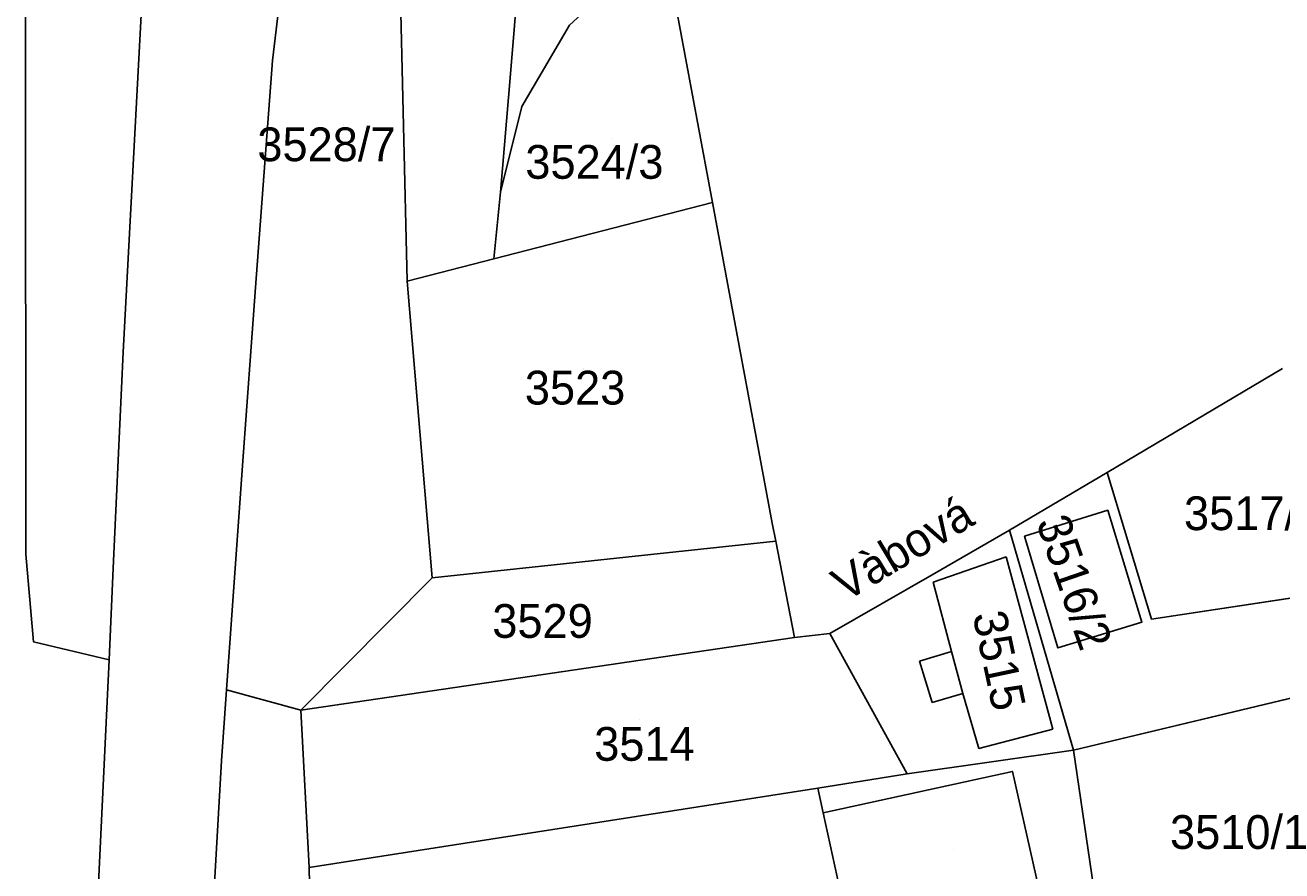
# Model space of a CAD drawing. Extents: x -262657 to -261595, y -1238015 to -1237156.
# Drawn here: x -262343.6 to -262269.2, y -1237443.2 to -1237393.1 of the extents above; entities that cross this region are included whole.
import ezdxf

# ---------------------------------------------------------------- set-up
doc = ezdxf.new("R2010")
doc.units = 0
for name, color, linetype in [('body_kn', 7, 'Continuous'), ('kladpar_druhypozemkov', 7, 'Continuous'), ('kladpar_hranice', 7, 'Continuous'), ('kladpar_parcelnecisla', 7, 'Continuous'), ('kladpar_plochy', 7, 'Continuous'), ('popisy', 7, 'Continuous'), ('zappar_hrandruhpozemk', 7, 'Continuous')]:
    doc.layers.add(name, color=color, linetype=linetype)

msp = doc.modelspace()

# ---------------------------------------------------------------- linework, layer by layer
at = {"layer": 'body_kn'}
for p, q in [((-262311.42, -1237393.12), (-262311.42, -1237393.12)), ((-262329, -1237395.2), (-262329, -1237395.2)), ((-262314.91, -1237395.99), (-262314.91, -1237395.99)), ((-262314.24, -1237397.93), (-262314.24, -1237397.93)), ((-262315.49, -1237403.01), (-262315.49, -1237403.01)), ((-262302.95, -1237403.62), (-262302.95, -1237403.62)), ((-262315.9, -1237406.95), (-262315.9, -1237406.95)), ((-262330, -1237408.65), (-262330, -1237408.65)), ((-262321.02, -1237408.27), (-262321.02, -1237408.27)), ((-262337.84, -1237412.47), (-262337.84, -1237412.47)), ((-262330.77, -1237419.19), (-262330.77, -1237419.19)), ((-262279.58, -1237419.6), (-262279.58, -1237419.6)), ((-262279.54, -1237421.84), (-262279.54, -1237421.84)), ((-262299.41, -1237422.61), (-262299.41, -1237422.61)), ((-262285.36, -1237423.02), (-262285.36, -1237423.02)), ((-262284.46, -1237423.38), (-262284.46, -1237423.38)), ((-262284.46, -1237423.38), (-262284.46, -1237423.38)), ((-262299.2, -1237423.67), (-262299.2, -1237423.67)), ((-262343.6, -1237424.44), (-262343.6, -1237424.44)), ((-262285.55, -1237424.61), (-262285.55, -1237424.61)), ((-262285.55, -1237424.61), (-262285.55, -1237424.61)), ((-262338.44, -1237425.28), (-262338.44, -1237425.28)), ((-262289.93, -1237425.67), (-262289.93, -1237425.67)), ((-262319.55, -1237425.85), (-262319.55, -1237425.85)), ((-262319.55, -1237425.85), (-262319.55, -1237425.85)), ((-262289.87, -1237426.11), (-262289.87, -1237426.11)), ((-262277.51, -1237428.47), (-262277.51, -1237428.47)), ((-262276.94, -1237428.3), (-262276.94, -1237428.3)), ((-262298.09, -1237429.37), (-262298.09, -1237429.37)), ((-262295.99, -1237429.15), (-262295.99, -1237429.15)), ((-262343.15, -1237429.64), (-262343.15, -1237429.64)), ((-262288.79, -1237430.21), (-262288.79, -1237430.21)), ((-262288.79, -1237430.21), (-262288.79, -1237430.21)), ((-262282.5, -1237430), (-262282.5, -1237430)), ((-262338.68, -1237430.7), (-262338.68, -1237430.7)), ((-262290.68, -1237430.78), (-262290.68, -1237430.78)), ((-262331.73, -1237432.47), (-262331.73, -1237432.47)), ((-262331.73, -1237432.47), (-262331.73, -1237432.47)), ((-262338.79, -1237433.17), (-262338.79, -1237433.17)), ((-262288.11, -1237432.69), (-262288.11, -1237432.69)), ((-262327.33, -1237433.68), (-262327.33, -1237433.68)), ((-262327.33, -1237433.68), (-262327.33, -1237433.68)), ((-262289.93, -1237433.23), (-262289.93, -1237433.23)), ((-262282.78, -1237434.8), (-262282.78, -1237434.8)), ((-262287.17, -1237435.95), (-262287.17, -1237435.95)), ((-262281.57, -1237436.05), (-262281.57, -1237436.05)), ((-262281.57, -1237436.05), (-262281.57, -1237436.05)), ((-262332.03, -1237436.68), (-262332.03, -1237436.68)), ((-262291.42, -1237437.45), (-262291.42, -1237437.45)), ((-262291.42, -1237437.45), (-262291.42, -1237437.45)), ((-262285.18, -1237437.31), (-262285.18, -1237437.31)), ((-262296.71, -1237438.31), (-262296.71, -1237438.31)), ((-262296.39, -1237439.77), (-262296.39, -1237439.77)), ((-262326.82, -1237443.01), (-262326.82, -1237443.01)), ((-262326.82, -1237443.01), (-262326.82, -1237443.01))]:
    msp.add_line(p, q, dxfattribs=at)
at = {"layer": 'kladpar_druhypozemkov'}
for p, q in [((-262324.82, -1237398.99), (-262324.82, -1237398.99)), ((-262308.92, -1237399.81), (-262308.92, -1237399.81)), ((-262310.6, -1237413.45), (-262310.6, -1237413.45)), ((-262271.41, -1237420.77), (-262271.41, -1237420.77)), ((-262280.17, -1237425.44), (-262280.17, -1237425.44)), ((-262312.44, -1237427.3), (-262312.44, -1237427.3)), ((-262285.33, -1237430.67), (-262285.33, -1237430.67)), ((-262307.25, -1237434.21), (-262307.25, -1237434.21)), ((-262271.75, -1237439.82), (-262271.75, -1237439.82)), ((-262288.7, -1237441.95), (-262288.7, -1237441.95))]:
    msp.add_line(p, q, dxfattribs=at)
at = {"layer": 'kladpar_hranice'}
for points in [[(-262343.34, -1237325.34), (-262331.8, -1237325.22), (-262331.36, -1237325.22), (-262332.05, -1237331.96), (-262333.22, -1237346.71), (-262335.95, -1237382.2), (-262336.73, -1237391.76), (-262337.84, -1237412.47), (-262338.44, -1237425.28), (-262338.68, -1237430.7), (-262343.15, -1237429.64), (-262343.6, -1237424.44), (-262343.65, -1237365.15), (-262343.34, -1237325.34)], [(-262331.73, -1237432.47), (-262330.77, -1237419.19), (-262330, -1237408.65), (-262329, -1237395.2), (-262326.86, -1237377.31), (-262323.22, -1237345.32), (-262321.9, -1237333.72), (-262320.95, -1237325.18), (-262318.82, -1237325.43), (-262321.14, -1237350.11), (-262321.67, -1237380.66), (-262321.02, -1237408.27), (-262319.55, -1237425.85), (-262327.33, -1237433.68), (-262331.73, -1237432.47)], [(-262321.14, -1237350.11), (-262318.82, -1237325.43), (-262312.37, -1237325.84), (-262308.92, -1237326.35), (-262309.26, -1237330), (-262311.14, -1237350.45), (-262311.85, -1237358.99), (-262314.91, -1237395.99), (-262315.49, -1237403.01), (-262315.9, -1237406.95), (-262321.02, -1237408.27), (-262321.67, -1237380.66), (-262321.14, -1237350.11)], [(-262343.65, -1237365.15), (-262343.6, -1237424.44), (-262343.15, -1237429.64), (-262338.68, -1237430.7), (-262338.79, -1237433.17), (-262339.94, -1237457.24), (-262341.34, -1237486.23), (-262339.66, -1237536.38)], [(-262326.86, -1237377.31), (-262329, -1237395.2), (-262330, -1237408.65), (-262330.77, -1237419.19), (-262331.73, -1237432.47), (-262332.03, -1237436.68), (-262333.57, -1237463.66), (-262334.8, -1237485.25), (-262334.58, -1237488.96), (-262332.58, -1237535.43), (-262332.11, -1237546.54), (-262332.06, -1237547.64), (-262339.28, -1237547.74), (-262339.33, -1237546.39), (-262339.66, -1237536.38), (-262341.34, -1237486.23), (-262339.94, -1237457.24), (-262338.79, -1237433.17), (-262338.68, -1237430.7), (-262338.44, -1237425.28), (-262337.84, -1237412.47), (-262336.73, -1237391.76)], [(-262305.73, -1237388.67), (-262302.95, -1237403.62), (-262315.9, -1237406.95), (-262315.49, -1237403.01), (-262314.24, -1237397.93), (-262311.42, -1237393.12), (-262308.04, -1237389.99), (-262305.73, -1237388.67)], [(-262319.55, -1237425.85), (-262321.02, -1237408.27), (-262315.9, -1237406.95), (-262302.95, -1237403.62), (-262299.41, -1237422.61), (-262299.2, -1237423.67), (-262319.55, -1237425.85)], [(-262246.97, -1237418.61), (-262264.1, -1237422.33), (-262263.27, -1237426.22), (-262276.94, -1237428.3), (-262279.58, -1237419.6), (-262269.18, -1237413.45)], [(-262279.58, -1237419.6), (-262276.94, -1237428.3), (-262263.27, -1237426.22), (-262264.1, -1237422.33), (-262246.97, -1237418.61), (-262240.68, -1237425.74), (-262259.16, -1237430.63), (-262260.46, -1237430.96), (-262262.7, -1237431.53), (-262281.57, -1237436.05)], [(-262281.57, -1237436.05), (-262285.36, -1237423.02), (-262279.58, -1237419.6)], [(-262279.54, -1237421.84), (-262284.46, -1237423.38), (-262282.5, -1237430), (-262277.51, -1237428.47), (-262279.54, -1237421.84)], [(-262284.46, -1237423.38), (-262279.54, -1237421.84), (-262277.51, -1237428.47), (-262282.5, -1237430), (-262284.46, -1237423.38)], [(-262291.42, -1237437.45), (-262295.99, -1237429.15), (-262289.93, -1237425.67), (-262285.36, -1237423.02), (-262281.57, -1237436.05), (-262291.42, -1237437.45)], [(-262327.33, -1237433.68), (-262319.55, -1237425.85), (-262299.2, -1237423.67), (-262298.09, -1237429.37), (-262327.33, -1237433.68)], [(-262326.82, -1237443.01), (-262327.33, -1237433.68), (-262298.09, -1237429.37), (-262295.99, -1237429.15), (-262291.42, -1237437.45), (-262296.71, -1237438.31), (-262326.82, -1237443.01)], [(-262281.57, -1237436.05), (-262262.7, -1237431.53), (-262261.1, -1237437.34), (-262258.95, -1237436.83), (-262257.9, -1237436.55), (-262256.26, -1237443.07), (-262235.03, -1237440.39), (-262237.65, -1237443.96), (-262256.96, -1237446.38), (-262279.63, -1237449.24), (-262281.57, -1237436.05)], [(-262331.73, -1237432.47), (-262327.33, -1237433.68), (-262326.82, -1237443.01), (-262326.27, -1237469.57), (-262326.03, -1237481.62), (-262325.93, -1237482.92), (-262325.3, -1237501.49), (-262324.89, -1237514.36), (-262325.13, -1237524.79), (-262325.13, -1237534.95), (-262332.58, -1237535.43), (-262334.58, -1237488.96), (-262334.8, -1237485.25), (-262333.57, -1237463.66), (-262332.03, -1237436.68), (-262331.73, -1237432.47)], [(-262289.69, -1237464.84), (-262290.86, -1237464.97), (-262293.89, -1237451.17), (-262294.17, -1237449.87), (-262296.39, -1237439.77), (-262296.71, -1237438.31), (-262291.42, -1237437.45), (-262281.57, -1237436.05), (-262279.63, -1237449.24), (-262277.44, -1237463.14), (-262289.69, -1237464.84)], [(-262326.27, -1237469.57), (-262326.82, -1237443.01), (-262296.71, -1237438.31), (-262296.39, -1237439.77), (-262294.17, -1237449.87), (-262293.89, -1237451.17), (-262290.86, -1237464.97), (-262321.56, -1237468.96), (-262326.27, -1237469.57)]]:
    msp.add_lwpolyline(points, dxfattribs=at)
at = {"layer": 'kladpar_plochy'}
for p, q in [((-262279.58, -1237419.6), (-262269.18, -1237413.45)), ((-262285.36, -1237423.02), (-262279.58, -1237419.6)), ((-262276.94, -1237428.3), (-262279.58, -1237419.6)), ((-262279.58, -1237419.6), (-262276.94, -1237428.3)), ((-262279.54, -1237421.84), (-262284.46, -1237423.38)), ((-262277.51, -1237428.47), (-262279.54, -1237421.84)), ((-262281.57, -1237436.05), (-262285.36, -1237423.02)), ((-262284.46, -1237423.38), (-262282.5, -1237430)), ((-262263.27, -1237426.22), (-262276.94, -1237428.3)), ((-262276.94, -1237428.3), (-262263.27, -1237426.22)), ((-262282.5, -1237430), (-262277.51, -1237428.47)), ((-262262.7, -1237431.53), (-262281.57, -1237436.05))]:
    msp.add_line(p, q, dxfattribs=at)
for points in [[(-262343.34, -1237325.34), (-262331.8, -1237325.22), (-262331.36, -1237325.22), (-262332.05, -1237331.96), (-262333.22, -1237346.71), (-262335.95, -1237382.2), (-262336.73, -1237391.76), (-262337.84, -1237412.47), (-262338.44, -1237425.28), (-262338.68, -1237430.7), (-262343.15, -1237429.64), (-262343.6, -1237424.44), (-262343.65, -1237365.15)], [(-262331.73, -1237432.47), (-262330.77, -1237419.19), (-262330, -1237408.65), (-262329, -1237395.2), (-262326.86, -1237377.31), (-262323.22, -1237345.32), (-262321.9, -1237333.72), (-262320.95, -1237325.18), (-262318.82, -1237325.43), (-262321.14, -1237350.11), (-262321.67, -1237380.66), (-262321.02, -1237408.27), (-262319.55, -1237425.85), (-262327.33, -1237433.68)], [(-262321.14, -1237350.11), (-262318.82, -1237325.43), (-262312.37, -1237325.84), (-262308.92, -1237326.35), (-262309.26, -1237330), (-262311.14, -1237350.45), (-262311.85, -1237358.99), (-262314.91, -1237395.99), (-262315.49, -1237403.01), (-262315.9, -1237406.95), (-262321.02, -1237408.27), (-262321.67, -1237380.66)], [(-262305.73, -1237388.67), (-262302.95, -1237403.62), (-262315.9, -1237406.95), (-262315.49, -1237403.01), (-262314.24, -1237397.93), (-262311.42, -1237393.12), (-262308.04, -1237389.99)], [(-262319.55, -1237425.85), (-262321.02, -1237408.27), (-262315.9, -1237406.95), (-262302.95, -1237403.62), (-262299.41, -1237422.61), (-262299.2, -1237423.67)], [(-262284.46, -1237423.38), (-262279.54, -1237421.84), (-262277.51, -1237428.47), (-262282.5, -1237430)], [(-262291.42, -1237437.45), (-262295.99, -1237429.15), (-262289.93, -1237425.67), (-262285.36, -1237423.02), (-262281.57, -1237436.05)], [(-262327.33, -1237433.68), (-262319.55, -1237425.85), (-262299.2, -1237423.67), (-262298.09, -1237429.37)], [(-262326.82, -1237443.01), (-262327.33, -1237433.68), (-262298.09, -1237429.37), (-262295.99, -1237429.15), (-262291.42, -1237437.45), (-262296.71, -1237438.31)], [(-262281.57, -1237436.05), (-262262.7, -1237431.53), (-262261.1, -1237437.34), (-262258.95, -1237436.83), (-262257.9, -1237436.55), (-262256.26, -1237443.07), (-262235.03, -1237440.39), (-262237.65, -1237443.96), (-262256.96, -1237446.38), (-262279.63, -1237449.24)], [(-262331.73, -1237432.47), (-262327.33, -1237433.68), (-262326.82, -1237443.01), (-262326.27, -1237469.57), (-262326.03, -1237481.62), (-262325.93, -1237482.92), (-262325.3, -1237501.49), (-262324.89, -1237514.36), (-262325.13, -1237524.79), (-262325.13, -1237534.95), (-262332.58, -1237535.43), (-262334.58, -1237488.96), (-262334.8, -1237485.25), (-262333.57, -1237463.66), (-262332.03, -1237436.68)], [(-262289.69, -1237464.84), (-262290.86, -1237464.97), (-262293.89, -1237451.17), (-262294.17, -1237449.87), (-262296.39, -1237439.77), (-262296.71, -1237438.31), (-262291.42, -1237437.45), (-262281.57, -1237436.05), (-262279.63, -1237449.24), (-262277.44, -1237463.14)], [(-262326.27, -1237469.57), (-262326.82, -1237443.01), (-262296.71, -1237438.31), (-262296.39, -1237439.77), (-262294.17, -1237449.87), (-262293.89, -1237451.17), (-262290.86, -1237464.97), (-262321.56, -1237468.96)]]:
    msp.add_lwpolyline(points, close=True, dxfattribs=at)
for points in [[(-262343.65, -1237365.15), (-262343.6, -1237424.44), (-262343.15, -1237429.64), (-262338.68, -1237430.7), (-262338.79, -1237433.17), (-262339.94, -1237457.24), (-262341.34, -1237486.23), (-262339.66, -1237536.38)], [(-262326.86, -1237377.31), (-262329, -1237395.2), (-262330, -1237408.65), (-262330.77, -1237419.19), (-262331.73, -1237432.47), (-262332.03, -1237436.68), (-262333.57, -1237463.66), (-262334.8, -1237485.25), (-262334.58, -1237488.96), (-262332.58, -1237535.43), (-262332.11, -1237546.54), (-262332.06, -1237547.64), (-262339.28, -1237547.74), (-262339.33, -1237546.39), (-262339.66, -1237536.38), (-262341.34, -1237486.23), (-262339.94, -1237457.24), (-262338.79, -1237433.17), (-262338.68, -1237430.7), (-262338.44, -1237425.28), (-262337.84, -1237412.47), (-262336.73, -1237391.76)]]:
    msp.add_lwpolyline(points, dxfattribs=at)
at = {"layer": 'zappar_hrandruhpozemk'}
for p, q in [((-262285.55, -1237424.61), (-262282.78, -1237434.8)), ((-262288.79, -1237430.21), (-262288.11, -1237432.69)), ((-262289.93, -1237433.23), (-262290.68, -1237430.78))]:
    msp.add_line(p, q, dxfattribs=at)
for points in [[(-262290.68, -1237430.78), (-262288.79, -1237430.21), (-262289.87, -1237426.11), (-262285.55, -1237424.61)], [(-262282.78, -1237434.8), (-262287.17, -1237435.95), (-262288.11, -1237432.69), (-262289.93, -1237433.23)], [(-262285.61, -1237450.85), (-262286.31, -1237448.15), (-262282.91, -1237447.41), (-262285.18, -1237437.31), (-262296.39, -1237439.77)]]:
    msp.add_lwpolyline(points, dxfattribs=at)

# ---------------------------------------------------------------- texts
at = {"layer": 'kladpar_parcelnecisla'}
for s, p in [('3528/7', (-262329.898, -1237401.17)), ('3524/3', (-262314.027, -1237402.21)), ('3523', (-262314.057, -1237415.58)), ('3517/1', (-262275.021, -1237423.02)), ('3529', (-262315.984, -1237429.4)), ('3514', (-262309.948, -1237436.68)), ('3510/1', (-262275.85, -1237441.9))]:
    msp.add_text(s, height=2, dxfattribs=at).set_placement(p)
for s, rotation, p in [('3516/2', 289, (-262283.791, -1237422.546)), ('3515', 282, (-262287.554, -1237428.028))]:
    msp.add_text(s, height=2, rotation=rotation, dxfattribs=at).set_placement(p)
at = {"layer": 'popisy'}
msp.add_text('Vàbová', height=2, rotation=31, dxfattribs=at).set_placement((-262295.072, -1237427.296))

doc.saveas('drawing.dxf')
